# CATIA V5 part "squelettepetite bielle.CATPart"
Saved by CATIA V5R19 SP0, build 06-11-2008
Part number: squelette petite bielle
Bounding box of the stored display mesh (mm): x 0 to 0, y 0 to 0, z -14 to 0
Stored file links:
  C:\Users\Gauthier\Documents\IFMA\IAO\TP2\squelettepetite bielle.CATPart
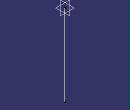
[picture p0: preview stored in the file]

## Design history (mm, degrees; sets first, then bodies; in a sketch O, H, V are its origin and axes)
Set1
  Line1: type PtPt, SecondPoint Point2, FirstPoint Point1
  Point1: stored without definition
  Point2: stored without definition
Body1 (main body)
